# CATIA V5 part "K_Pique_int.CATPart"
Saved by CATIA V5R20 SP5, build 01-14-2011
Part number: Pique int
Bounding box of the stored display mesh (mm): x 0 to 340, y -11 to 11, z -10.984 to 10.984
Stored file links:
  G:\Khaled_CFAO_2011\ST2M\ST2M_GR2\amorin\Khaled\CAD_Modification\K_Pique_int.CATPart
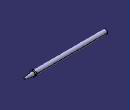
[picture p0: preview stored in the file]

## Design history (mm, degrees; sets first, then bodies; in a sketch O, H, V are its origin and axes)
Body1 (main body)
  Sketch1 on yz-plane, origin (0, 0, 0), H (0, 1, 0), V (0, 0, 1)
    circle A1 centre (0, 0) radius 9
  Pad1: profile Sketch1, direction (1, 0, 0), length 300
  Sketch2 on end face of Pad1, origin (300, 0, 0), H (0, 1, 0), V (0, 0, 1)
    circle A1 centre (0, 0) radius 11
  Pad2: profile Sketch2, direction (1, 0, 0), length 5
  Sketch3 on zx-plane, origin (0, 0, 0), H (-1, 0, 0), V (0, 0, 1)
    line L1 (-305, 8) -> (-340, 3)
    point P1 (-305, 8)
    line L2 (-340, 3) -> (-340, 0)
    point P3 (-340, 0)
    line L3 (-305, 8) -> (-305, 0)
    point P4 (-305, 8)
    point P5 (-305, 0)
    coincidence: P3 H, P4 L1, P5 H, P1 P4
    vertical: L2 V, L3 V
  Shaft1: profile Sketch3, axis axis of face of Pad1 from Sketch1.A1, angle 360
